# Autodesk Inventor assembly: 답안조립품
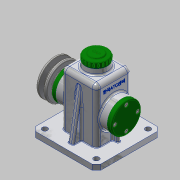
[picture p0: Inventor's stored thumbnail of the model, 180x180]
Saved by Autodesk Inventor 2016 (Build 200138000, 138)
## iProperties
Created: 2018-10
Part Number: 답안조립품
Material: 일반
Document SubType Name: Assembly
Designer: user
Author: user
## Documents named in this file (14)
- C:\Users\user\Desktop\481016V1011\답안조립품.iam
- C:\Users\user\Desktop\481016V1011\본체.ipt
- C:\Users\user\Desktop\481016V1011\뒤커버.ipt
- C:\Users\user\Desktop\481016V1011\앞커버.ipt
- C:\Users\user\Desktop\481016V1011\상부캡.ipt
- C:\Users\user\Desktop\481016V1011\V-벨트풀리.ipt
- C:\Users\user\Desktop\481016V1011\볼트 M6 x 12.ipt
- C:\Users\user\Desktop\481016V1011\오일실 15 25 7.ipt
- C:\Users\user\Desktop\481016V1011\축.ipt
- C:\Users\user\Desktop\481016V1011\키 5 x 5 x 14.ipt
- C:\Users\user\Desktop\481016V1011\와셔.ipt
- C:\Users\user\Desktop\481016V1011\멈춤링 15 x 1.ipt
- C:\Users\user\Desktop\481016V1011\베어링 15 x 35 x 11.ipt
- C:\Users\user\Desktop\481016V1011\볼트 M4 x 10.ipt
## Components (1 placed, 1 different names)
1. V-벨트풀리:1
